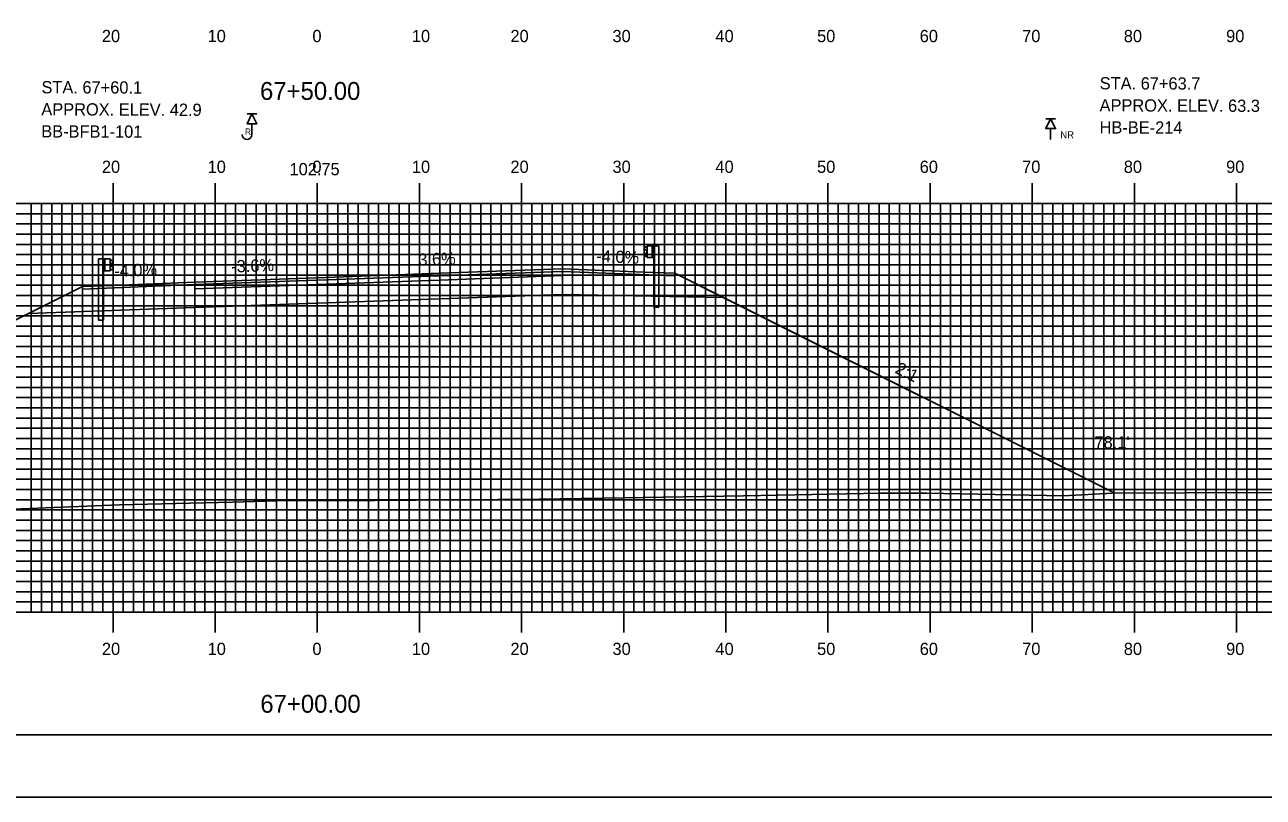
# Model space of a CAD drawing. Extents: x 1759430 to 1759773, y 442591 to 442811.
# Drawn here: x 1759567 to 1759688.3, y 442590.5 to 442666.2 of the extents above; entities that cross this region are included whole.
import ezdxf

# ---------------------------------------------------------------- set-up
doc = ezdxf.new("R2010")
doc.units = 0
for name, color, linetype in [('ANNOTATION', 7, 'Continuous'), ('BORDER', 7, 'Continuous'), ('BORING - NO REFUSAL', 7, 'Continuous'), ('BORING - REFUSAL', 7, 'Continuous'), ('D_Guardrail_Beam_Lt', 7, 'Continuous'), ('D_Guardrail_Beam_Rt', 7, 'Continuous'), ('D_Roadway_Centerline', 7, 'Continuous'), ('D_Roadway_Centerline_Text', 7, 'Continuous'), ('D_Roadway_Edge_Shoulder', 7, 'Continuous'), ('D_Roadway_Edge_TW', 7, 'Continuous'), ('D_Roadway_Pavement', 7, 'Continuous'), ('D_Roadway_SlopeLines', 7, 'Continuous'), ('D_Roadway_SubGrade', 7, 'Continuous'), ('D_Text_Standard', 7, 'Continuous'), ('H_V ANNOTATION', 7, 'Continuous'), ('MAJOR', 7, 'Continuous'), ('MINOR', 7, 'Continuous'), ('PLOT BOUNDARY', 7, 'Continuous'), ('S_Roadway_Centerline', 7, 'Continuous')]:
    doc.layers.add(name, color=color, linetype=linetype)

msp = doc.modelspace()

# ---------------------------------------------------------------- linework, layer by layer
at = {"layer": 'BORDER'}
msp.add_lwpolyline([(1759446.07, 442596.67), (1759766.07, 442596.67), (1759766.07, 442806.67), (1759446.07, 442806.67)], close=True, dxfattribs=at)
at = {"layer": 'BORING - NO REFUSAL'}
for p, q in [((1759667.95, 442656.97), (1759666.99, 442656.97)), ((1759667.47, 442656.01), (1759667.47, 442654.95))]:
    msp.add_line(p, q, dxfattribs=at)
msp.add_lwpolyline([(1759667.47, 442656.97), (1759667.95, 442656.01), (1759666.99, 442656.01)], close=True, dxfattribs=at)
at = {"layer": 'BORING - REFUSAL'}
for p, q in [((1759589.75, 442657.45), (1759588.79, 442657.45)), ((1759589.27, 442656.49), (1759589.27, 442655.43))]:
    msp.add_line(p, q, dxfattribs=at)
msp.add_lwpolyline([(1759589.27, 442657.45), (1759589.75, 442656.49), (1759588.79, 442656.49)], close=True, dxfattribs=at)
msp.add_arc((1759588.79, 442655.43), 0.485, 180, 0, dxfattribs=at)
at = {"layer": 'D_Guardrail_Beam_Lt'}
for p, q in [((1759574.25, 442643.25), (1759574.25, 442637.25)), ((1759574.72, 442643.25), (1759574.25, 442643.25)), ((1759575.4, 442643.25), (1759574.72, 442643.25)), ((1759574.72, 442643.25), (1759574.72, 442642.08)), ((1759574.78, 442643.25), (1759574.78, 442642.08)), ((1759574.88, 442643.25), (1759574.88, 442642.08)), ((1759575.4, 442642.08), (1759575.4, 442643.25)), ((1759575.4, 442643.16), (1759575.48, 442643.15)), ((1759575.49, 442643.14), (1759575.64, 442643.04)), ((1759574.72, 442642.08), (1759575.4, 442642.08)), ((1759574.74, 442637.25), (1759574.74, 442642.08)), ((1759575.48, 442642.18), (1759575.4, 442642.16)), ((1759575.41, 442642.7), (1759575.41, 442642.63)), ((1759575.64, 442642.9), (1759575.44, 442642.76)), ((1759575.44, 442642.56), (1759575.64, 442642.43)), ((1759575.64, 442642.28), (1759575.49, 442642.18)), ((1759574.74, 442637.25), (1759574.25, 442637.25))]:
    msp.add_line(p, q, dxfattribs=at)
for centre, major_axis, start_param, end_param in [((1759575.47, 442643.11), (0.0417, 0), 0.959931, 1.376053), ((1759575.49, 442642.7), (-0.0789, 0), 5.323254, 6.283185), ((1759575.49, 442642.63), (-0.0789, 0), 6.283185, 7.243116), ((1759575.47, 442642.22), (0.0417, 0), 4.907132, 5.323254), ((1759575.59, 442642.97), (0.0877, 0), 5.323254, 7.243116), ((1759575.59, 442642.36), (0.0877, 0), 5.323254, 7.243116)]:
    msp.add_ellipse(centre, major_axis=major_axis, ratio=0.995501, start_param=start_param, end_param=end_param, dxfattribs=at)
at = {"layer": 'D_Guardrail_Beam_Rt'}
for p, q in [((1759627.86, 442644.44), (1759627.71, 442644.34)), ((1759627.95, 442644.46), (1759627.87, 442644.44)), ((1759627.95, 442644.54), (1759628.63, 442644.54)), ((1759627.95, 442643.38), (1759627.95, 442644.54)), ((1759628.47, 442644.54), (1759628.47, 442643.38)), ((1759628.57, 442644.54), (1759628.57, 442643.38)), ((1759628.63, 442644.54), (1759629.1, 442644.54)), ((1759628.63, 442644.54), (1759628.63, 442643.38)), ((1759629.1, 442644.54), (1759629.1, 442638.54)), ((1759627.71, 442644.19), (1759627.91, 442644.06)), ((1759627.91, 442643.86), (1759627.71, 442643.72)), ((1759627.71, 442643.58), (1759627.86, 442643.48)), ((1759627.87, 442643.47), (1759627.95, 442643.46)), ((1759627.94, 442643.99), (1759627.94, 442643.92)), ((1759628.63, 442643.38), (1759627.95, 442643.38)), ((1759628.61, 442638.54), (1759628.61, 442643.38)), ((1759628.61, 442638.54), (1759629.1, 442638.54))]:
    msp.add_line(p, q, dxfattribs=at)
for centre, major_axis, start_param, end_param in [((1759627.76, 442644.27), (-0.0877, 0), 5.323254, 7.243116), ((1759627.88, 442644.4), (-0.0417, 0), 4.907132, 5.323254), ((1759627.76, 442643.65), (-0.0877, 0), 5.323254, 7.243116), ((1759627.88, 442643.51), (-0.0417, 0), 0.959931, 1.376053), ((1759627.86, 442643.99), (0.0789, 0), 0, 0.959931), ((1759627.86, 442643.92), (0.0789, 0), 5.323254, 6.283185)]:
    msp.add_ellipse(centre, major_axis=major_axis, ratio=0.995501, start_param=start_param, end_param=end_param, dxfattribs=at)
at = {"layer": 'D_Roadway_Centerline'}
msp.add_lwpolyline([(1759530.5, 442619.46), (1759567.38, 442637.9), (1759572.67, 442640.54), (1759575.67, 442640.66), (1759583.67, 442640.98), (1759595.67, 442641.41), (1759607.67, 442641.85), (1759619.67, 442642.28), (1759627.67, 442641.96), (1759630.67, 442641.84), (1759635.42, 442639.46), (1759673.76, 442620.3)], dxfattribs=at)
at = {"layer": 'D_Roadway_Edge_Shoulder'}
for points in [[(1759619.67, 442642.28), (1759627.67, 442641.96), (1759627.67, 442641.96), (1759630.67, 442641.84), (1759630.67, 442641.59), (1759619.67, 442642.03)], [(1759583.67, 442640.98), (1759575.67, 442640.66), (1759575.67, 442640.66), (1759572.67, 442640.54), (1759572.67, 442640.29), (1759583.67, 442640.73)]]:
    msp.add_lwpolyline(points, close=True, dxfattribs=at)
at = {"layer": 'D_Roadway_Edge_TW'}
for points in [[(1759607.67, 442641.85), (1759619.67, 442642.28), (1759619.67, 442642.03), (1759607.67, 442641.6)], [(1759583.67, 442640.73), (1759583.67, 442640.98), (1759595.67, 442641.41), (1759607.67, 442641.85), (1759607.67, 442641.6), (1759595.67, 442641.16)]]:
    msp.add_lwpolyline(points, close=True, dxfattribs=at)
at = {"layer": 'D_Roadway_Pavement'}
for points in [[(1759607.67, 442641.6), (1759619.67, 442642.03), (1759619.67, 442641.61), (1759607.67, 442641.18)], [(1759583.67, 442640.32), (1759583.67, 442640.73), (1759595.67, 442641.16), (1759607.67, 442641.6), (1759607.67, 442641.18), (1759595.67, 442640.75)]]:
    msp.add_lwpolyline(points, close=True, dxfattribs=at)
for points in [[(1759619.67, 442642.03), (1759619.67, 442641.61)], [(1759619.67, 442642.03), (1759619.67, 442641.61)], [(1759583.67, 442640.73), (1759583.67, 442640.32)]]:
    msp.add_lwpolyline(points, dxfattribs=at)
at = {"layer": 'D_Roadway_SlopeLines'}
for points in [[(1759630.67, 442641.84), (1759673.76, 442620.3)], [(1759572.67, 442640.54), (1759530.5, 442619.46)]]:
    msp.add_lwpolyline(points, dxfattribs=at)
at = {"layer": 'D_Roadway_SubGrade'}
for points in [[(1759619.67, 442641.61), (1759619.67, 442642.03), (1759630.67, 442641.59), (1759630.67, 442641.84), (1759635.42, 442639.46), (1759619.67, 442639.78)], [(1759583.67, 442640.32), (1759583.67, 442640.73), (1759572.67, 442640.29), (1759572.67, 442640.54), (1759567.38, 442637.9), (1759583.67, 442638.48)], [(1759583.67, 442638.48), (1759583.67, 442640.32), (1759595.67, 442640.75), (1759607.67, 442641.18), (1759607.67, 442639.35), (1759595.67, 442638.91)], [(1759607.67, 442641.18), (1759619.67, 442641.61), (1759619.67, 442639.78), (1759607.67, 442639.35)]]:
    msp.add_lwpolyline(points, close=True, dxfattribs=at)
at = {"layer": 'MAJOR'}
for p, q in [((1759575.67, 442650.67), (1759575.67, 442648.67)), ((1759585.67, 442650.67), (1759585.67, 442648.67)), ((1759595.67, 442650.67), (1759595.67, 442648.67)), ((1759605.67, 442650.67), (1759605.67, 442648.67)), ((1759615.67, 442650.67), (1759615.67, 442648.67)), ((1759625.67, 442650.67), (1759625.67, 442648.67)), ((1759635.67, 442650.67), (1759635.67, 442648.67)), ((1759645.67, 442650.67), (1759645.67, 442648.67)), ((1759655.67, 442650.67), (1759655.67, 442648.67)), ((1759665.67, 442650.67), (1759665.67, 442648.67)), ((1759675.67, 442650.67), (1759675.67, 442648.67)), ((1759685.67, 442650.67), (1759685.67, 442648.67)), ((1759455.67, 442648.67), (1759735.67, 442648.67)), ((1759455.67, 442648.67), (1759735.67, 442648.67)), ((1759575.67, 442608.67), (1759575.67, 442648.67)), ((1759585.67, 442608.67), (1759585.67, 442648.67)), ((1759595.67, 442608.67), (1759595.67, 442648.67)), ((1759605.67, 442608.67), (1759605.67, 442648.67)), ((1759615.67, 442608.67), (1759615.67, 442648.67)), ((1759625.67, 442608.67), (1759625.67, 442648.67)), ((1759635.67, 442608.67), (1759635.67, 442648.67)), ((1759645.67, 442608.67), (1759645.67, 442648.67)), ((1759655.67, 442608.67), (1759655.67, 442648.67)), ((1759665.67, 442608.67), (1759665.67, 442648.67)), ((1759675.67, 442608.67), (1759675.67, 442648.67)), ((1759685.67, 442608.67), (1759685.67, 442648.67)), ((1759455.67, 442643.67), (1759735.67, 442643.67)), ((1759455.67, 442638.67), (1759735.67, 442638.67)), ((1759455.67, 442633.67), (1759735.67, 442633.67)), ((1759455.67, 442628.67), (1759735.67, 442628.67)), ((1759455.67, 442623.67), (1759735.67, 442623.67)), ((1759455.67, 442618.67), (1759735.67, 442618.67)), ((1759455.67, 442613.67), (1759735.67, 442613.67)), ((1759455.67, 442608.67), (1759735.67, 442608.67)), ((1759455.67, 442608.67), (1759735.67, 442608.67)), ((1759575.67, 442606.66), (1759575.67, 442608.67)), ((1759585.67, 442606.66), (1759585.67, 442608.67)), ((1759595.67, 442606.66), (1759595.67, 442608.67)), ((1759605.67, 442606.66), (1759605.67, 442608.67)), ((1759615.67, 442606.66), (1759615.67, 442608.67)), ((1759625.67, 442606.66), (1759625.67, 442608.67)), ((1759635.67, 442606.66), (1759635.67, 442608.67)), ((1759645.67, 442606.66), (1759645.67, 442608.67)), ((1759655.67, 442606.66), (1759655.67, 442608.67)), ((1759665.67, 442606.66), (1759665.67, 442608.67)), ((1759675.67, 442606.66), (1759675.67, 442608.67)), ((1759685.67, 442606.66), (1759685.67, 442608.67))]:
    msp.add_line(p, q, dxfattribs=at)
at = {"layer": 'MINOR'}
for p, q in [((1759567.67, 442608.67), (1759567.67, 442648.67)), ((1759568.67, 442608.67), (1759568.67, 442648.67)), ((1759569.67, 442608.67), (1759569.67, 442648.67)), ((1759570.67, 442608.67), (1759570.67, 442648.67)), ((1759571.67, 442608.67), (1759571.67, 442648.67)), ((1759572.67, 442608.67), (1759572.67, 442648.67)), ((1759573.67, 442608.67), (1759573.67, 442648.67)), ((1759574.67, 442608.67), (1759574.67, 442648.67)), ((1759576.67, 442608.67), (1759576.67, 442648.67)), ((1759577.67, 442608.67), (1759577.67, 442648.67)), ((1759578.67, 442608.67), (1759578.67, 442648.67)), ((1759579.67, 442608.67), (1759579.67, 442648.67)), ((1759580.67, 442608.67), (1759580.67, 442648.67)), ((1759581.67, 442608.67), (1759581.67, 442648.67)), ((1759582.67, 442608.67), (1759582.67, 442648.67)), ((1759583.67, 442608.67), (1759583.67, 442648.67)), ((1759584.67, 442608.67), (1759584.67, 442648.67)), ((1759586.67, 442608.67), (1759586.67, 442648.67)), ((1759587.67, 442608.67), (1759587.67, 442648.67)), ((1759588.67, 442608.67), (1759588.67, 442648.67)), ((1759589.67, 442608.67), (1759589.67, 442648.67)), ((1759590.67, 442608.67), (1759590.67, 442648.67)), ((1759591.67, 442608.67), (1759591.67, 442648.67)), ((1759592.67, 442608.67), (1759592.67, 442648.67)), ((1759593.67, 442608.67), (1759593.67, 442648.67)), ((1759594.67, 442608.67), (1759594.67, 442648.67)), ((1759596.67, 442608.67), (1759596.67, 442648.67)), ((1759597.67, 442608.67), (1759597.67, 442648.67)), ((1759598.67, 442608.67), (1759598.67, 442648.67)), ((1759599.67, 442608.67), (1759599.67, 442648.67)), ((1759600.67, 442608.67), (1759600.67, 442648.67)), ((1759601.67, 442608.67), (1759601.67, 442648.67)), ((1759602.67, 442608.67), (1759602.67, 442648.67)), ((1759603.67, 442608.67), (1759603.67, 442648.67)), ((1759604.67, 442608.67), (1759604.67, 442648.67)), ((1759606.67, 442608.67), (1759606.67, 442648.67)), ((1759607.67, 442608.67), (1759607.67, 442648.67)), ((1759608.67, 442608.67), (1759608.67, 442648.67)), ((1759609.67, 442608.67), (1759609.67, 442648.67)), ((1759610.67, 442608.67), (1759610.67, 442648.67)), ((1759611.67, 442608.67), (1759611.67, 442648.67)), ((1759612.67, 442608.67), (1759612.67, 442648.67)), ((1759613.67, 442608.67), (1759613.67, 442648.67)), ((1759614.67, 442608.67), (1759614.67, 442648.67)), ((1759616.67, 442608.67), (1759616.67, 442648.67)), ((1759617.67, 442608.67), (1759617.67, 442648.67)), ((1759618.67, 442608.67), (1759618.67, 442648.67)), ((1759619.67, 442608.67), (1759619.67, 442648.67)), ((1759620.67, 442608.67), (1759620.67, 442648.67)), ((1759621.67, 442608.67), (1759621.67, 442648.67)), ((1759622.67, 442608.67), (1759622.67, 442648.67)), ((1759623.67, 442608.67), (1759623.67, 442648.67)), ((1759624.67, 442608.67), (1759624.67, 442648.67)), ((1759626.67, 442608.67), (1759626.67, 442648.67)), ((1759627.67, 442608.67), (1759627.67, 442648.67)), ((1759628.67, 442608.67), (1759628.67, 442648.67)), ((1759629.67, 442608.67), (1759629.67, 442648.67)), ((1759630.67, 442608.67), (1759630.67, 442648.67)), ((1759631.67, 442608.67), (1759631.67, 442648.67)), ((1759632.67, 442608.67), (1759632.67, 442648.67)), ((1759633.67, 442608.67), (1759633.67, 442648.67)), ((1759634.67, 442608.67), (1759634.67, 442648.67)), ((1759636.67, 442608.67), (1759636.67, 442648.67)), ((1759637.67, 442608.67), (1759637.67, 442648.67)), ((1759638.67, 442608.67), (1759638.67, 442648.67)), ((1759639.67, 442608.67), (1759639.67, 442648.67)), ((1759640.67, 442608.67), (1759640.67, 442648.67)), ((1759641.67, 442608.67), (1759641.67, 442648.67)), ((1759642.67, 442608.67), (1759642.67, 442648.67)), ((1759643.67, 442608.67), (1759643.67, 442648.67)), ((1759644.67, 442608.67), (1759644.67, 442648.67)), ((1759646.67, 442608.67), (1759646.67, 442648.67)), ((1759647.67, 442608.67), (1759647.67, 442648.67)), ((1759648.67, 442608.67), (1759648.67, 442648.67)), ((1759649.67, 442608.67), (1759649.67, 442648.67)), ((1759650.67, 442608.67), (1759650.67, 442648.67)), ((1759651.67, 442608.67), (1759651.67, 442648.67)), ((1759652.67, 442608.67), (1759652.67, 442648.67)), ((1759653.67, 442608.67), (1759653.67, 442648.67)), ((1759654.67, 442608.67), (1759654.67, 442648.67)), ((1759656.67, 442608.67), (1759656.67, 442648.67)), ((1759657.67, 442608.67), (1759657.67, 442648.67)), ((1759658.67, 442608.67), (1759658.67, 442648.67)), ((1759659.67, 442608.67), (1759659.67, 442648.67)), ((1759660.67, 442608.67), (1759660.67, 442648.67)), ((1759661.67, 442608.67), (1759661.67, 442648.67)), ((1759662.67, 442608.67), (1759662.67, 442648.67)), ((1759663.67, 442608.67), (1759663.67, 442648.67)), ((1759664.67, 442608.67), (1759664.67, 442648.67)), ((1759666.67, 442608.67), (1759666.67, 442648.67)), ((1759667.67, 442608.67), (1759667.67, 442648.67)), ((1759668.67, 442608.67), (1759668.67, 442648.67)), ((1759669.67, 442608.67), (1759669.67, 442648.67)), ((1759670.67, 442608.67), (1759670.67, 442648.67)), ((1759671.67, 442608.67), (1759671.67, 442648.67)), ((1759672.67, 442608.67), (1759672.67, 442648.67)), ((1759673.67, 442608.67), (1759673.67, 442648.67)), ((1759674.67, 442608.67), (1759674.67, 442648.67)), ((1759676.67, 442608.67), (1759676.67, 442648.67)), ((1759677.67, 442608.67), (1759677.67, 442648.67)), ((1759678.67, 442608.67), (1759678.67, 442648.67)), ((1759679.67, 442608.67), (1759679.67, 442648.67)), ((1759680.67, 442608.67), (1759680.67, 442648.67)), ((1759681.67, 442608.67), (1759681.67, 442648.67)), ((1759682.67, 442608.67), (1759682.67, 442648.67)), ((1759683.67, 442608.67), (1759683.67, 442648.67)), ((1759684.67, 442608.67), (1759684.67, 442648.67)), ((1759686.67, 442608.67), (1759686.67, 442648.67)), ((1759687.67, 442608.67), (1759687.67, 442648.67)), ((1759455.67, 442647.67), (1759735.67, 442647.67)), ((1759455.67, 442646.67), (1759735.67, 442646.67)), ((1759455.67, 442645.67), (1759735.67, 442645.67)), ((1759455.67, 442644.67), (1759735.67, 442644.67)), ((1759455.67, 442642.67), (1759735.67, 442642.67)), ((1759455.67, 442641.67), (1759735.67, 442641.67)), ((1759455.67, 442640.67), (1759735.67, 442640.67)), ((1759455.67, 442639.67), (1759735.67, 442639.67)), ((1759455.67, 442637.67), (1759735.67, 442637.67)), ((1759455.67, 442636.67), (1759735.67, 442636.67)), ((1759455.67, 442635.67), (1759735.67, 442635.67)), ((1759455.67, 442634.67), (1759735.67, 442634.67)), ((1759455.67, 442632.67), (1759735.67, 442632.67)), ((1759455.67, 442631.67), (1759735.67, 442631.67)), ((1759455.67, 442630.67), (1759735.67, 442630.67)), ((1759455.67, 442629.67), (1759735.67, 442629.67)), ((1759455.67, 442627.67), (1759735.67, 442627.67)), ((1759455.67, 442626.67), (1759735.67, 442626.67)), ((1759455.67, 442625.67), (1759735.67, 442625.67)), ((1759455.67, 442624.67), (1759735.67, 442624.67)), ((1759455.67, 442622.67), (1759735.67, 442622.67)), ((1759455.67, 442621.67), (1759735.67, 442621.67)), ((1759455.67, 442620.67), (1759735.67, 442620.67)), ((1759455.67, 442619.67), (1759735.67, 442619.67)), ((1759455.67, 442617.67), (1759735.67, 442617.67)), ((1759455.67, 442616.67), (1759735.67, 442616.67)), ((1759455.67, 442615.67), (1759735.67, 442615.67)), ((1759455.67, 442614.67), (1759735.67, 442614.67)), ((1759455.67, 442612.67), (1759735.67, 442612.67)), ((1759455.67, 442611.67), (1759735.67, 442611.67)), ((1759455.67, 442610.67), (1759735.67, 442610.67)), ((1759455.67, 442609.67), (1759735.67, 442609.67))]:
    msp.add_line(p, q, dxfattribs=at)
at = {"layer": 'PLOT BOUNDARY'}
msp.add_lwpolyline([(1759429.89, 442590.55), (1759769.89, 442590.55), (1759769.89, 442810.55), (1759429.89, 442810.55)], close=True, dxfattribs=at)
at = {"layer": 'S_Roadway_Centerline'}
msp.add_lwpolyline([(1759561.87, 442618.6), (1759576.31, 442619.17), (1759587.34, 442619.44), (1759592.69, 442619.59), (1759597.58, 442619.6), (1759601.3, 442619.59), (1759617.37, 442619.72), (1759625.63, 442619.86), (1759637.41, 442620.07), (1759650.85, 442620.3), (1759655.33, 442620.3), (1759668.72, 442620.04), (1759673.51, 442620.3), (1759687.82, 442620.37), (1759698.03, 442620.27), (1759719.4, 442620.37), (1759724.82, 442620.36), (1759726.86, 442620.44), (1759730.9, 442620.21), (1759732.4, 442619.56), (1759735.56, 442619.02), (1759735.67, 442619.01)], dxfattribs=at)

# ---------------------------------------------------------------- texts
at = {"layer": 'ANNOTATION'}
for s, rotation, p in [('-3.6%', 2.0618, (1759587.26, 442641.91)), ('3.6%', 2.0618, (1759605.58, 442642.57)), ('-4.0%', 357.7094, (1759622.97, 442642.95)), ('-4.0%', 2.2906, (1759575.81, 442641.47)), ('2:1', 333.4349, (1759652.15, 442632.14))]:
    msp.add_text(s, height=1.2, rotation=rotation, dxfattribs=at).set_placement(p)
at = {"layer": 'BORING - NO REFUSAL'}
for s, p in [('STA. 67+63.7', (1759672.27, 442659.85)), ('APPROX. ELEV. 63.3', (1759672.26, 442657.69)), ('HB-BE-214', (1759672.26, 442655.53))]:
    msp.add_text(s, height=1.2, rotation=359.8142, dxfattribs=at).set_placement(p)
msp.add_text('NR', height=0.7, dxfattribs=at).set_placement((1759668.41, 442655.05))
at = {"layer": 'BORING - REFUSAL'}
for s, p in [('STA. 67+60.1', (1759568.66, 442659.46)), ('APPROX. ELEV. 42.9', (1759568.65, 442657.3)), ('BB-BFB1-101', (1759568.64, 442655.14))]:
    msp.add_text(s, height=1.2, rotation=359.8142, dxfattribs=at).set_placement(p)
msp.add_text('R', height=0.64, dxfattribs=at).set_placement((1759588.57, 442655.38))
at = {"layer": 'D_Roadway_Centerline'}
for s in ['C', 'L']:
    msp.add_text(s, height=0.0146, dxfattribs=at).set_placement((1759595.67, 442641.41))
at = {"layer": 'D_Roadway_Centerline_Text'}
msp.add_text('102.75', height=1.2, dxfattribs=at).set_placement((1759592.95, 442651.44))
at = {"layer": 'D_Text_Standard'}
msp.add_text("78.1'", height=1.2, dxfattribs=at).set_placement((1759671.76, 442624.69))
at = {"layer": 'H_V ANNOTATION'}
for s, height, p in [('20', 1.2, (1759574.58, 442664.47)), ('10', 1.2, (1759584.93, 442664.47)), ('0', 1.2, (1759595.19, 442664.47)), ('10', 1.2, (1759604.93, 442664.47)), ('20', 1.2, (1759614.58, 442664.47)), ('30', 1.2, (1759624.57, 442664.47)), ('40', 1.2, (1759634.65, 442664.47)), ('50', 1.2, (1759644.6, 442664.47)), ('60', 1.2, (1759654.65, 442664.47)), ('70', 1.2, (1759664.68, 442664.47)), ('80', 1.2, (1759674.63, 442664.47)), ('90', 1.2, (1759684.65, 442664.47)), ('67+50.00', 1.75, (1759590.06, 442658.82)), ('20', 1.2, (1759574.58, 442651.67)), ('10', 1.2, (1759584.93, 442651.67)), ('0', 1.2, (1759595.19, 442651.67)), ('10', 1.2, (1759604.93, 442651.67)), ('20', 1.2, (1759614.58, 442651.67)), ('30', 1.2, (1759624.57, 442651.67)), ('40', 1.2, (1759634.65, 442651.67)), ('50', 1.2, (1759644.6, 442651.67)), ('60', 1.2, (1759654.65, 442651.67)), ('70', 1.2, (1759664.68, 442651.67)), ('80', 1.2, (1759674.63, 442651.67)), ('90', 1.2, (1759684.65, 442651.67)), ('20', 1.2, (1759574.58, 442604.47)), ('10', 1.2, (1759584.93, 442604.47)), ('0', 1.2, (1759595.19, 442604.47)), ('10', 1.2, (1759604.93, 442604.47)), ('20', 1.2, (1759614.58, 442604.47)), ('30', 1.2, (1759624.57, 442604.47)), ('40', 1.2, (1759634.65, 442604.47)), ('50', 1.2, (1759644.6, 442604.47)), ('60', 1.2, (1759654.65, 442604.47)), ('70', 1.2, (1759664.68, 442604.47)), ('80', 1.2, (1759674.63, 442604.47)), ('90', 1.2, (1759684.65, 442604.47)), ('67+00.00', 1.75, (1759590.09, 442598.82))]:
    msp.add_text(s, height=height, dxfattribs=at).set_placement(p)

doc.saveas('drawing.dxf')
